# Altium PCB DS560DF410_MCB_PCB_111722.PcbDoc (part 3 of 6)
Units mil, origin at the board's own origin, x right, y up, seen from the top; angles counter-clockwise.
Board outline 5500 x 5000 mil, 6 copper layers (Top Layer, L2_GND1, L3_SIG1, L4_PWR1, L5_GND2, Bottom Layer), stack 61.748 mil thick; 297 components, 231 nets, 1236 pads, 998 vias.
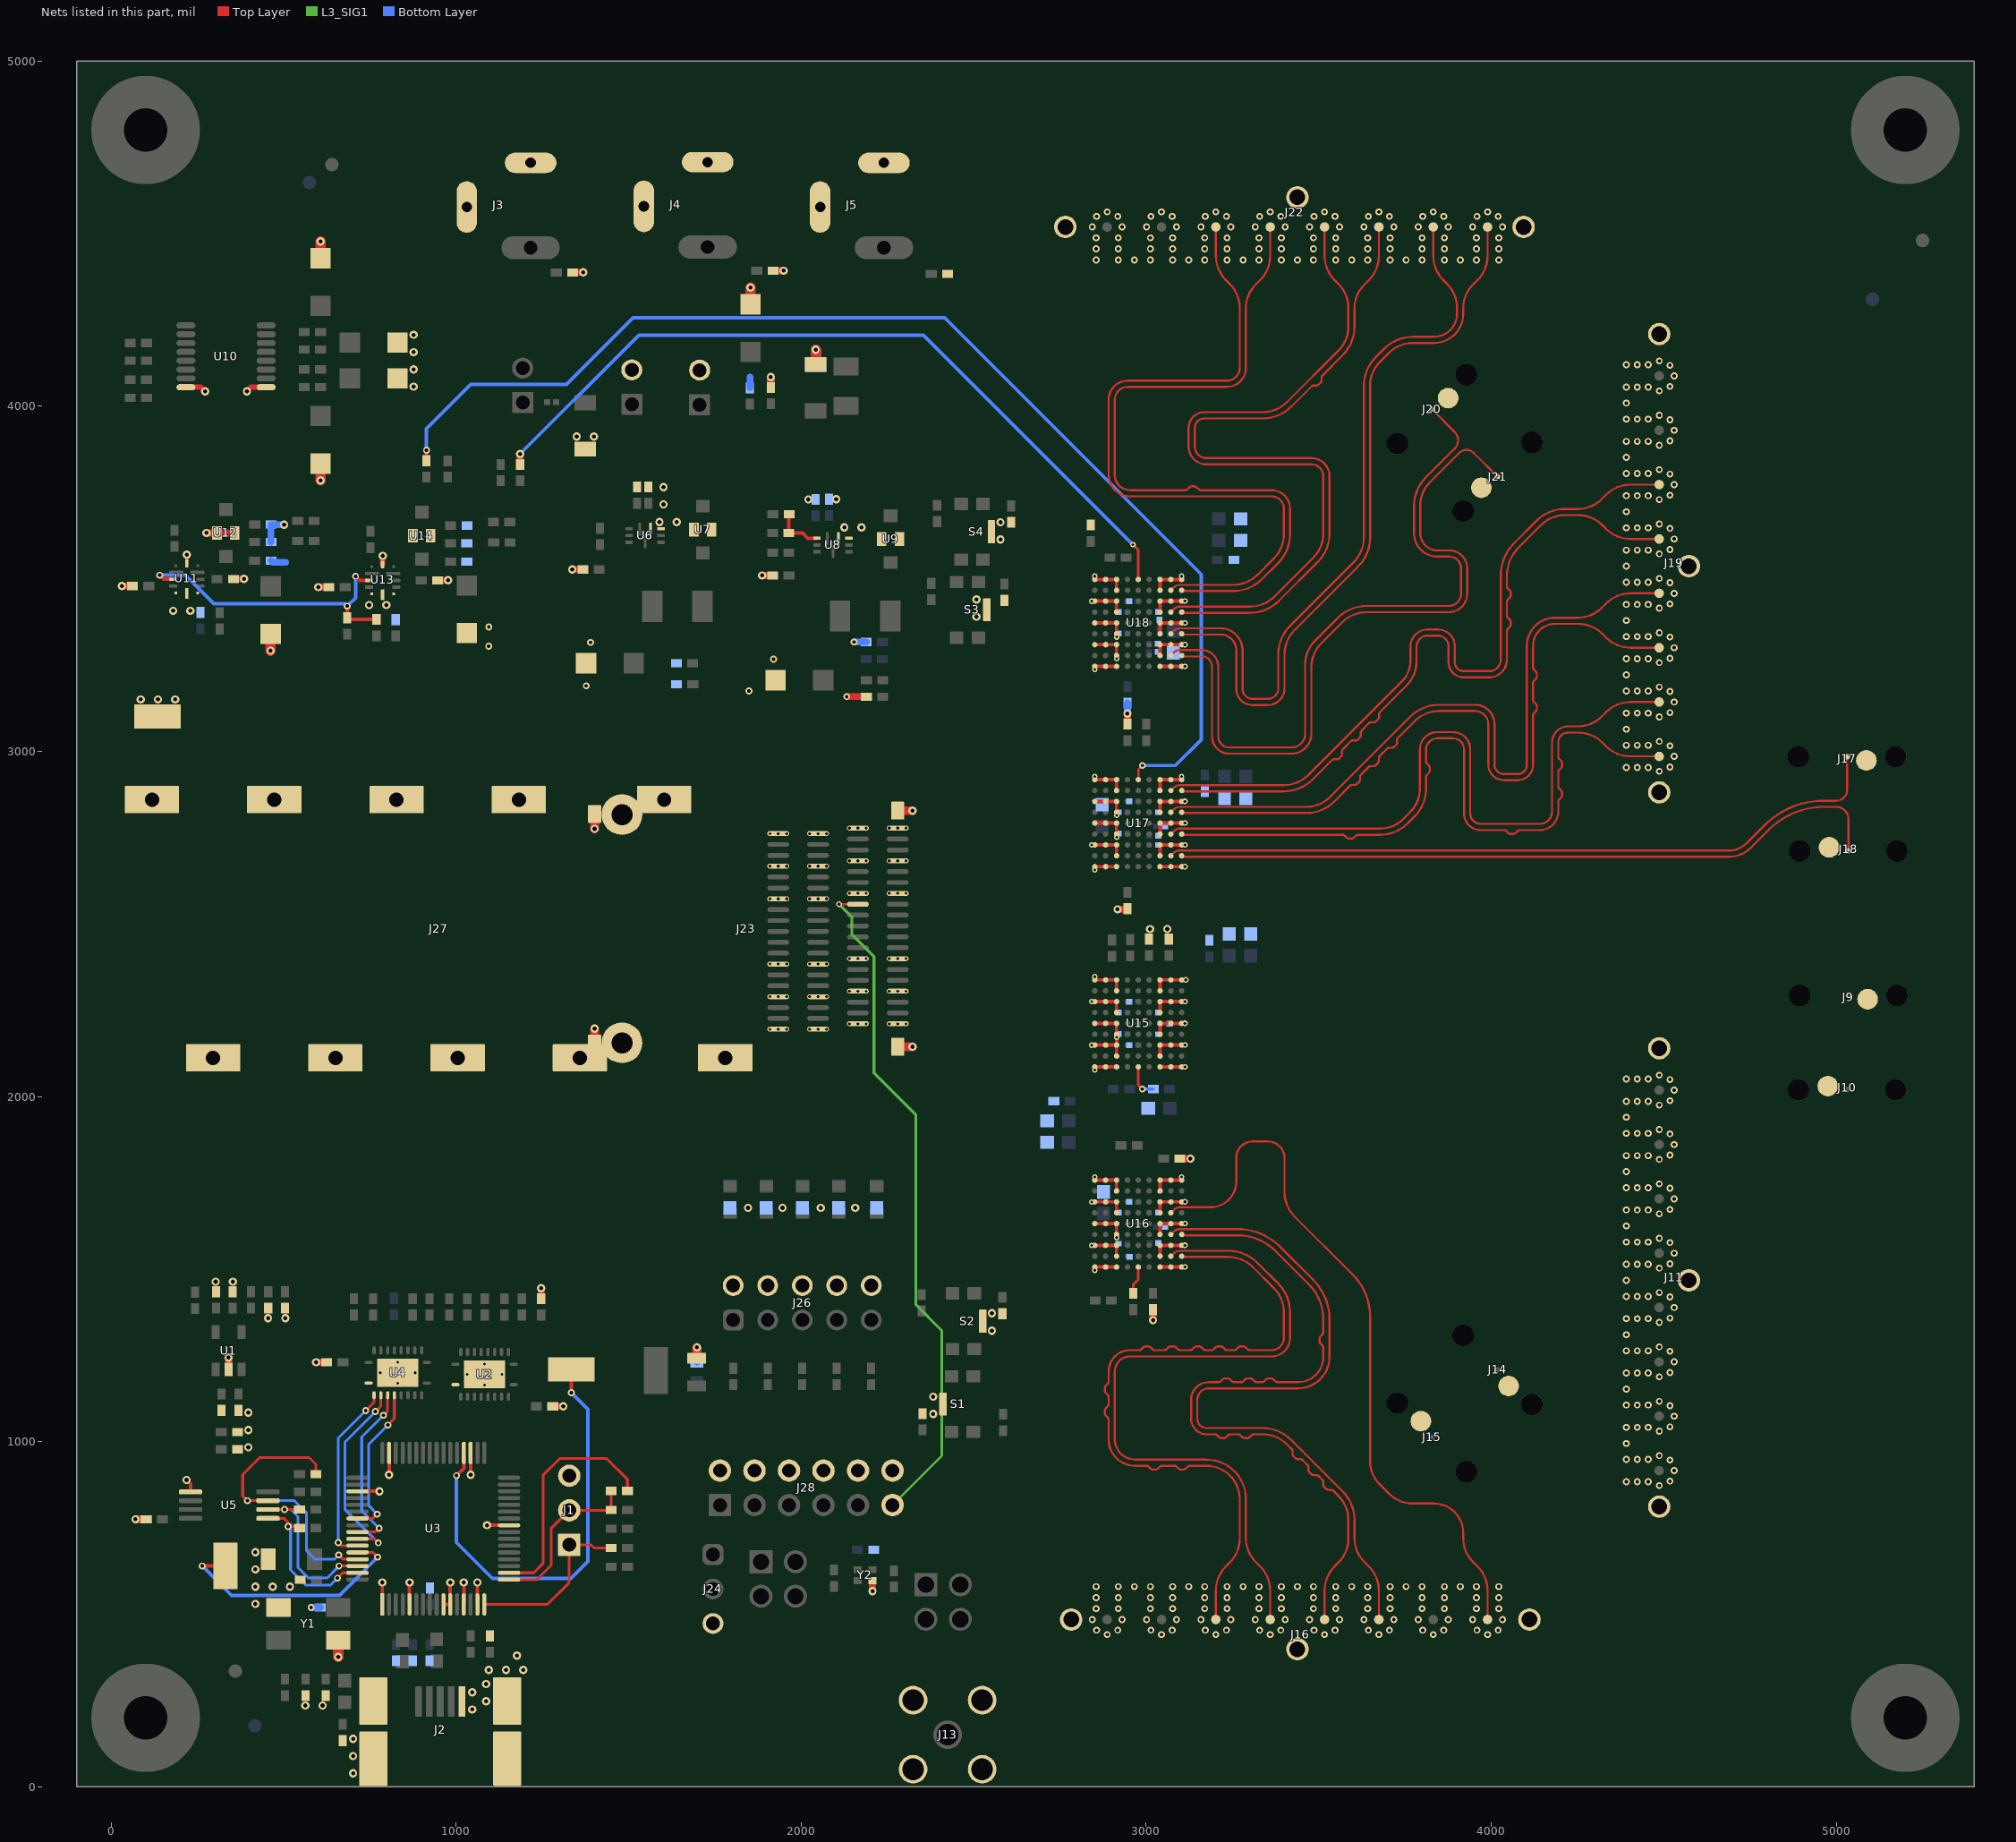
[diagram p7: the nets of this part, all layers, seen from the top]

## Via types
v1: diameter 20, hole 10, Top Layer to Bottom Layer, 380 vias
v2: diameter 24, hole 12, Top Layer to Bottom Layer, tented both sides, 226 vias
v3: diameter 20, hole 10, Top Layer to Bottom Layer, tented both sides, 162 vias
v4: diameter 14, hole 8.1, Top Layer to Bottom Layer, tented both sides, 88 vias
v5: diameter 16, hole 8.1, Top Layer to Bottom Layer, tented both sides, 84 vias
v6: diameter 16, hole 8, Top Layer to Bottom Layer, tented both sides, 34 vias
v7: diameter 15, hole 8.1, Top Layer to Bottom Layer, tented both sides, 16 vias
v8: diameter 19.68, hole 7.87, Top Layer to Bottom Layer, tented both sides, 8 vias

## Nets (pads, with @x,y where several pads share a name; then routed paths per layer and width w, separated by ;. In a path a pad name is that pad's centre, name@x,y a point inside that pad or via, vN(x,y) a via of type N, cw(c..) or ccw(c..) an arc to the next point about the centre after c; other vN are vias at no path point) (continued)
CON_RX6P: J16.1 U16.H6 | length 2123.7
  Top Layer w6: U16.H6@3071.49,1663.14 3079.81,1671.46 cw(c3097.74,1653.53) 3097.74,1678.89 3185.79,1678.89 ccw(c3185.79,1754.2) 3261.1,1754.2 3261.1,1820.78 ; 3261.1,1822.78 cw(c3308,1822.78) 3308,1869.68 3352.58,1869.68 cw(c3352.58,1821.46) 3400.8,1821.46 3400.8,1722.87 ccw(c3500.8,1722.87) 3430.09,1652.16 3598.79,1483.46 cw(c3478.3,1362.97) 3648.7,1362.97 3648.7,945.32 ccw(c3748.7,945.32) 3677.99,874.61 3702.68,849.92 ccw(c3773.39,920.63) 3773.39,820.63 3834.08,820.63 cw(c3834.08,735.95) 3918.76,735.95 3918.76,719.64 ccw(c4014.95,719.64) 3946.93,651.62 3960,638.56 cw(c3889.29,567.85) 3989.29,567.85 J16.1@3989.29,484.47
CON_RX7N: J16.4 U16.J4 | length 2125.8
  Top Layer w6: U16.J4@3102.98,1600.15 ccw(c3108.42,1605.59) 3108.42,1597.9 3265.01,1597.9 cw(c3265.01,1443.66) 3374.08,1552.72 3471.4,1455.4 cw(c3370.5,1354.49) 3513.2,1354.49 3513.2,1316.68 cw(c3504.47,1316.68) 3510.64,1310.5 3505.84,1305.7 ccw(c3514.81,1296.73) 3502.12,1296.73 3502.12,1291.46 ccw(c3514.36,1291.46) 3505.7,1282.81 3510.64,1277.88 cw(c3504.47,1271.7) 3513.2,1271.7 3513.2,1245.49 cw(c3439.97,1245.49) 3439.97,1172.26 3380.58,1172.26 cw(c3380.58,1180.99) 3374.4,1174.82 3369.6,1179.62 ccw(c3360.63,1170.65) 3360.63,1183.34 3355.36,1183.34 ccw(c3355.36,1171.1) 3346.71,1179.75 3341.78,1174.82 cw(c3335.6,1180.99) 3335.6,1172.26 3320.18,1172.26 cw(c3320.18,1180.99) 3314,1174.82 3309.2,1179.62 ccw(c3300.23,1170.65) 3300.23,1183.34 3294.96,1183.34 ccw(c3294.96,1171.1) 3286.31,1179.75 3281.38,1174.82 cw(c3275.2,1180.99) 3275.2,1172.26 3254.68,1172.26 cw(c3254.68,1180.99) 3248.5,1174.82 3243.7,1179.62 ccw(c3234.73,1170.65) 3234.73,1183.34 3229.46,1183.34 ccw(c3229.46,1171.1) 3220.81,1179.75 3215.88,1174.82 cw(c3209.7,1180.99) 3209.7,1172.26 3181.41,1172.26 ccw(c3181.41,1120.85) 3130,1120.85 3130,1066.4 ccw(c3175.2,1066.4) 3175.2,1021.2 3198.9,1021.2 cw(c3198.9,1012.47) 3205.08,1018.64 3210.01,1013.7 ccw(c3218.66,1022.36) 3218.66,1010.12 3223.93,1010.12 ccw(c3223.93,1022.81) 3232.9,1013.84 3237.7,1018.64 cw(c3243.88,1012.47) 3243.88,1021.2 3266.8,1021.2 cw(c3266.8,1012.47) 3272.98,1018.64 3277.91,1013.7 ccw(c3286.56,1022.36) 3286.56,1010.12 3291.83,1010.12 ccw(c3291.83,1022.81) 3300.8,1013.84 3305.6,1018.64 cw(c3311.78,1012.47) 3311.78,1021.2 3337.18,1021.2 cw(c3337.18,921.2) 3407.89,991.91 3421.43,978.37 cw(c3415.25,972.2) 3423.99,972.2 3423.99,965.21 ccw(c3436.22,965.21) 3427.57,956.56 3431.29,952.84 ccw(c3440.26,961.81) 3440.26,949.12 3447.06,949.12 cw(c3447.06,940.39) 3453.23,946.57 3467.74,932.06 cw(c3461.57,925.88) 3470.3,925.88 3470.3,918.9 ccw(c3482.54,918.9) 3473.89,910.25 3477.61,906.52 ccw(c3486.58,915.49) 3486.58,902.81 3493.37,902.81 cw(c3493.37,894.07) 3499.55,900.25 3510.45,889.35 cw(c3504.28,883.17) 3513.01,883.17 3513.01,876.19 ccw(c3525.25,876.19) 3516.59,867.54 3520.32,863.81 ; J16.4@3516.84,484.47 3516.84,567.85 cw(c3616.84,567.85) 3546.13,638.56 3556.51,648.93 ccw(c3485.8,719.64) 3585.8,719.64 3585.8,772.58 ccw(c3485.8,772.58) 3556.51,843.29 3542.26,857.54 ccw(c3536.08,851.37) 3536.08,860.1 3529.29,860.1 cw(c3529.29,872.78) 3520.33,863.8
CON_RX7P: J16.3 U16.H4 | length 2125.4
  Top Layer w6: U16.H4@3071.49,1600.15 3079.81,1608.47 cw(c3097.74,1590.54) 3097.74,1615.9 3265.01,1615.9 cw(c3265.01,1443.66) 3386.8,1565.46 3484.13,1468.12 cw(c3370.5,1354.49) 3531.2,1354.49 3531.2,1245.49 cw(c3439.97,1245.49) 3439.97,1154.26 3181.41,1154.26 ; J16.3@3674.33,484.47 3674.33,567.85 ccw(c3574.33,567.85) 3645.04,638.56 3631.97,651.62 cw(c3699.99,719.64) 3603.8,719.64 3603.8,772.58 ccw(c3485.8,772.58) 3569.24,856.02 3420.61,1004.64 ccw(c3337.18,921.2) 3337.18,1039.2 3175.2,1039.2 cw(c3175.2,1066.4) 3148,1066.4 3148,1120.85 cw(c3181.41,1120.85) 3181,1154.26 ; 3181,1154.26 cw(c3181.41,1120.85) 3181.41,1154.26 ; 3181,1154.26 3181.41,1154.26
CON_RX8N: J16.6 U16.J2 | length 2126.2
  Top Layer w6: U16.J2@3102.98,1537.16 ccw(c3108.42,1542.59) 3108.42,1534.91 3238.37,1534.91 cw(c3238.37,1434.91) 3309.08,1505.62 3369.61,1445.09 cw(c3298.9,1374.38) 3398.9,1374.38 3398.9,1300.5 cw(c3363.4,1300.5) 3363.4,1265 3300.18,1265 cw(c3300.18,1273.73) 3294,1267.56 3289.07,1272.5 ccw(c3280.42,1263.84) 3280.42,1276.08 3275.15,1276.08 ccw(c3275.15,1263.39) 3266.18,1272.36 3261.38,1267.56 cw(c3255.2,1273.73) 3255.2,1265 3234.18,1265 cw(c3234.18,1273.73) 3228,1267.56 3223.07,1272.5 ccw(c3214.42,1263.84) 3214.42,1276.08 3209.15,1276.08 ccw(c3209.15,1263.39) 3200.18,1272.36 3195.38,1267.56 cw(c3189.2,1273.73) 3189.2,1265 3172.18,1265 cw(c3172.18,1273.73) 3166,1267.56 3161.07,1272.5 ccw(c3152.42,1263.84) 3152.42,1276.08 3147.15,1276.08 ccw(c3147.15,1263.39) 3138.18,1272.36 3133.38,1267.56 cw(c3127.2,1273.73) 3127.2,1265 3097.8,1265 cw(c3097.8,1273.73) 3091.62,1267.56 3086.82,1272.36 ccw(c3077.85,1263.39) 3077.85,1276.08 3072.58,1276.08 ccw(c3072.58,1263.84) 3063.93,1272.5 3059,1267.56 cw(c3052.82,1273.73) 3052.82,1265 3024.68,1265 cw(c3024.68,1273.73) 3018.5,1267.56 3013.57,1272.5 ccw(c3004.92,1263.84) 3004.92,1276.08 2999.65,1276.08 ccw(c2999.65,1263.39) 2990.68,1272.36 2985.88,1267.56 cw(c2979.7,1273.73) 2979.7,1265 2953.47,1265 ccw(c2953.47,1202.5) 2890.97,1202.5 2890.97,1173.9 cw(c2882.24,1173.9) 2888.41,1167.72 2883.6,1162.92 ccw(c2892.57,1153.95) 2879.89,1153.95 2879.89,1148.68 ccw(c2892.12,1148.68) 2883.47,1140.03 2888.41,1135.1 cw(c2882.24,1128.92) 2890.97,1128.92 2890.97,1108.4 cw(c2882.24,1108.4) 2888.41,1102.22 2883.6,1097.42 ccw(c2892.57,1088.45) 2879.89,1088.45 2879.89,1083.18 ccw(c2892.12,1083.18) 2883.47,1074.53 2888.41,1069.6 cw(c2882.24,1063.42) 2890.97,1063.42 2890.97,1006.51 ccw(c2967.58,1006.51) 2967.58,929.9 3000.7,929.9 cw(c3000.7,921.17) 3006.88,927.34 3011.68,922.54 ccw(c3020.65,931.51) 3020.65,918.82 3025.92,918.82 ccw(c3025.92,931.06) 3034.57,922.4 3039.5,927.34 cw(c3045.68,921.17) 3045.68,929.9 3081.9,929.9 cw(c3081.9,921.17) 3088.08,927.34 3092.88,922.54 ccw(c3101.85,931.51) 3101.85,918.82 3107.12,918.82 ccw(c3107.12,931.06) 3115.77,922.4 3120.7,927.34 cw(c3126.88,921.17) 3126.88,929.9 3174.38,929.9 cw(c3174.38,833.45) 3270.84,833.45 3270.84,719.64 cw(c3170.84,719.64) 3241.55,648.93 3231.17,638.56 ccw(c3301.88,567.85) 3201.88,567.85 J16.6@3201.88,484.47
CON_RX8P: J16.5 U16.H2 | length 2125.4
  Top Layer w6: U16.H2@3071.49,1537.16 3079.81,1545.48 cw(c3097.74,1527.55) 3097.74,1552.9 3238.37,1552.9 cw(c3238.37,1434.9) 3321.81,1518.35 3382.34,1457.81 cw(c3298.9,1374.38) 3416.9,1374.38 3416.9,1300.5 cw(c3363.4,1300.5) 3363.4,1247 2953.47,1247 ccw(c2953.47,1202.5) 2908.97,1202.5 2908.97,1006.51 ccw(c2967.58,1006.51) 2967.58,947.9 3174.38,947.9 cw(c3174.38,833.45) 3288.84,833.45 3288.84,719.64 ccw(c3385.03,719.64) 3317.01,651.62 3330.08,638.56 cw(c3259.36,567.85) 3359.36,567.85 J16.5@3359.36,484.47
CON_TX1N: J18.1 U17.A8 | length 2089.6
  Top Layer w6: U17.A8@3102.98,2697.39 ccw(c3110.46,2704.87) 3110.46,2694.3 4688.28,2694.3 ccw(c4688.28,2785.13) 4752.5,2720.9 4786.71,2755.11 ; 4788.19,2756.59 4804.42,2772.82 cw(c4963.58,2613.66) 4963.58,2838.75 5000.56,2838.75 cw(c5000.56,2804.43) 5034.89,2804.43 J18.1@5034.89,2711.31
CON_TX1P: J17.1 U17.B8 | length 2125.2
  Top Layer w6: U17.B8@3071.49,2697.39 3081.33,2707.23 cw(c3093.68,2694.88) 3093.68,2712.35 3114.94,2712.35 ; 3115.38,2712.3 4688.27,2712.3 ccw(c4688.27,2785.13) 4739.78,2733.63 4791.72,2785.57 cw(c4963.55,2613.74) 4963.55,2856.75 5000.56,2856.75 ccw(c5000.56,2887.34) 5031.15,2887.34 J17.1@5031.15,2984.18
CON_TX2N: J19.8 U17.A6 | length 2131.3
  Top Layer w6: 4082.7,2771.78 4083.34,2771.78 ; J19.8@4486.77,2985.27 4403.39,2985.27 cw(c4403.39,3085.27) 4332.68,3014.56 4322.31,3024.94 ccw(c4251.6,2954.23) 4251.6,3054.23 4222.65,3054.23 ccw(c4222.65,3025.58) 4194,3025.58 4194,2984.62 ccw(c4202.73,2984.62) 4196.56,2978.45 4201.42,2973.59 cw(c4192.58,2964.75) 4205.08,2964.75 4205.08,2959.52 cw(c4192.58,2959.52) 4201.42,2950.68 4196.56,2945.82 ccw(c4202.73,2939.65) 4194,2939.65 4194,2898.99 ccw(c4202.73,2898.99) 4196.56,2892.82 4201.42,2887.96 cw(c4192.58,2879.12) 4205.08,2879.12 4205.08,2873.88 cw(c4192.58,2873.88) 4201.42,2865.05 4196.56,2860.19 ccw(c4202.73,2854.01) 4194,2854.01 4194,2824.81 cw(c4140.98,2824.81) 4140.98,2771.78 4083.34,2771.78 ; U17.A6@3108.42,2758.13 cw(c3108.42,2765.82) U17.A6@3102.98,2760.39 ccw(c3108.42,2765.82) U17.A6@3108.42,2758.13 ; U17.A6@3108.42,2758.13 3567.64,2758.13 cw(c3567.64,2746.86) 3575.61,2754.83 3579.73,2750.71 ccw(c3588.57,2759.55) 3588.57,2747.06 3593.8,2747.06 ccw(c3593.8,2759.55) 3602.64,2750.71 3606.04,2754.11 cw(c3615.74,2744.41) 3615.74,2758.13 3678.37,2758.13 ccw(c3678.37,2869.23) 3756.93,2790.67 3778.24,2811.99 ccw(c3699.17,2891.07) 3811,2891.07 3811,2925.67 cw(c3819.73,2925.67) 3813.56,2931.84 3818.42,2936.7 ccw(c3809.58,2945.54) 3822.08,2945.54 3822.08,2950.77 ccw(c3809.58,2950.77) 3818.42,2959.61 3813.56,2964.47 cw(c3819.73,2970.65) 3811,2970.65 3811,3004.85 cw(c3843.79,3004.85) 3843.79,3037.65 3889.15,3037.65 cw(c3889.15,3005.8) 3921,3005.8 3921,2819.95 ccw(c3969.17,2819.95) 3969.17,2771.78 4037.16,2771.78 cw(c4037.16,2762.78) 4043.52,2769.15 4048.31,2764.36 ccw(c4057.14,2773.2) 4057.14,2760.7 4062.38,2760.7 ccw(c4062.38,2773.2) 4071.21,2764.36 4075.3,2768.45 cw(c4083.34,2760.41) 4083.34,2771.78
CON_TX2P: J19.7 U17.B6 | length 2125.5
  Top Layer w6: U17.B6@3071.49,2760.39 3079.81,2768.71 cw(c3097.74,2750.78) 3097.74,2776.13 3678.37,2776.13 ccw(c3678.37,2869.23) 3744.2,2803.4 3765.52,2824.72 ccw(c3699.17,2891.07) 3793,2891.07 3793,3004.85 cw(c3843.79,3004.85) 3843.79,3055.65 3889.15,3055.65 cw(c3889.15,3005.8) 3939,3005.8 3939,2819.95 ccw(c3969.17,2819.95) 3969.17,2789.78 4140.98,2789.78 ccw(c4140.98,2824.81) 4176,2824.81 4176,3025.58 cw(c4222.65,3025.58) 4222.65,3072.23 4251.6,3072.23 ccw(c4251.6,3168.42) 4319.62,3100.4 4332.68,3113.46 cw(c4403.39,3042.75) 4403.39,3142.75 J19.7@4486.77,3142.75
CON_TX3N: J19.6 U17.A4 | length 2130.8
  Top Layer w6: J19.6@4486.77,3300.23 4403.39,3300.23 cw(c4403.39,3400.23) 4332.68,3329.52 4322.31,3339.9 ccw(c4251.6,3269.19) 4251.6,3369.19 4184.72,3369.19 ccw(c4184.72,3305.56) 4121.1,3305.56 4121.1,3242.9 ccw(c4129.83,3242.9) 4123.66,3236.72 4128.52,3231.86 cw(c4119.68,3223.03) 4132.18,3223.03 4132.18,3217.79 cw(c4119.68,3217.79) 4128.52,3208.96 4124.02,3204.46 ccw(c4131.07,3197.41) 4121.1,3197.41 4121.1,3149.65 ccw(c4131.64,3149.65) 4124.19,3142.2 4128.52,3137.86 cw(c4119.68,3129.03) 4132.18,3129.03 4132.18,3123.79 cw(c4119.68,3123.79) 4128.52,3114.96 4124.47,3110.9 ccw(c4132.6,3102.78) 4121.1,3102.78 4121.1,2960.95 cw(c4076.5,2960.95) 4076.5,2916.35 4036.6,2916.35 cw(c4036.6,2961.65) 3991.3,2961.65 3991.3,3078.65 ccw(c3953.2,3078.65) 3953.2,3116.75 3848.55,3116.75 ccw(c3848.55,3016.75) 3777.84,3087.46 3729.88,3039.5 ccw(c3736.61,3032.77) 3727.1,3032.77 3727.1,3026.22 cw(c3714.6,3026.22) 3723.44,3017.38 3719.73,3013.68 cw(c3710.9,3022.52) 3710.9,3010.02 3704.66,3010.02 ccw(c3704.66,2999.76) 3697.4,3007.02 3677.21,2986.82 ccw(c3684.6,2979.43) 3674.15,2979.43 3674.15,2973.27 cw(c3661.65,2973.27) 3670.49,2964.43 3666.78,2960.73 cw(c3657.95,2969.57) 3657.95,2957.07 3651.63,2957.07 ccw(c3651.63,2947) 3644.51,2954.12 3622.67,2932.28 ccw(c3629.84,2925.11) 3619.7,2925.11 3619.7,2918.82 cw(c3607.2,2918.82) 3616.04,2909.98 3612.33,2906.28 cw(c3603.5,2915.12) 3603.5,2902.62 3597.23,2902.62 ccw(c3597.23,2892.43) 3590.02,2899.64 3544.38,2853.99 cw(c3465.03,2933.34) 3465.03,2821.13 U17.A4@3108.42,2821.13 ; U17.A4@3108.42,2821.13 cw(c3108.42,2828.81) U17.A4@3102.98,2823.38 ccw(c3108.42,2828.81) U17.A4@3108.42,2821.13
CON_TX3P: J19.5 U17.B4 | length 2125.8
  Top Layer w6: U17.B4@3071.49,2823.38 3079.81,2831.7 cw(c3097.74,2813.77) 3097.74,2839.13 3465.03,2839.13 ccw(c3465.03,2933.34) 3531.65,2866.72 3765.12,3100.19 cw(c3848.55,3016.75) 3848.55,3134.75 3953.2,3134.75 cw(c3953.2,3078.65) 4009.3,3078.65 4009.3,2961.65 ccw(c4036.6,2961.65) 4036.6,2934.35 4076.5,2934.35 ccw(c4076.5,2960.95) 4103.1,2960.95 4103.1,3305.56 cw(c4184.72,3305.56) 4184.72,3387.19 4251.6,3387.19 ccw(c4251.6,3483.38) 4319.62,3415.36 4332.68,3428.43 cw(c4403.39,3357.71) 4403.39,3457.71 J19.5@4486.77,3457.71
CON_TX4N: J19.4 U17.A2 | length 2131.3
  Top Layer w6: J19.4@4486.77,3615.19 4403.39,3615.2 cw(c4403.39,3715.2) 4332.68,3644.48 4322.31,3654.86 ccw(c4251.6,3584.15) 4251.6,3684.15 4213.92,3684.15 ccw(c4213.92,3584.15) 4143.21,3654.86 4080.27,3591.92 ccw(c4164.7,3507.49) 4045.3,3507.49 4045.3,3478.5 ccw(c4054.81,3478.5) 4048.09,3471.78 4053.17,3466.69 cw(c4045.42,3458.94) 4056.38,3458.94 4056.38,3452.75 cw(c4044.65,3452.75) 4052.94,3444.46 4048.31,3439.82 ccw(c4055.56,3432.56) 4045.3,3432.56 4045.3,3393.9 ccw(c4054.81,3393.9) 4048.09,3387.18 4052.97,3382.29 cw(c4044.75,3374.07) 4056.38,3374.07 4056.38,3367.96 cw(c4045.11,3367.96) 4053.08,3359.99 4048.31,3355.22 ccw(c4055.56,3347.96) 4045.3,3347.96 4045.3,3265.67 cw(c3993.77,3265.67) 3993.77,3214.15 3920.5,3214.15 cw(c3920.5,3258.45) 3876.2,3258.45 3876.2,3304.42 ccw(c3845.48,3304.42) 3845.48,3335.15 3815.92,3335.15 ccw(c3815.92,3302.62) 3783.4,3302.62 3783.4,3260.28 cw(c3685.07,3260.28) 3754.6,3190.74 3677.57,3113.71 ccw(c3684.29,3106.99) 3674.78,3106.99 3674.78,3099.35 cw(c3664.91,3099.35) 3671.89,3092.37 3667.27,3087.75 cw(c3658.79,3096.23) 3658.79,3084.24 3652.34,3084.24 ccw(c3652.34,3073.97) 3645.09,3081.23 3624.89,3061.04 ccw(c3632.28,3053.65) 3621.83,3053.65 3621.83,3046.95 cw(c3610.64,3046.95) 3618.55,3039.03 3613.71,3034.18 cw(c3606.71,3041.18) 3606.71,3031.29 3599.31,3031.29 ccw(c3599.31,3021.22) 3592.19,3028.34 3570.35,3006.5 ccw(c3577.52,2999.33) 3567.38,2999.33 3567.38,2992.14 cw(c3557.04,2992.14) 3564.36,2984.84 3559.22,2979.7 cw(c3552.32,2986.6) 3552.32,2976.84 3544.91,2976.84 ccw(c3544.91,2966.65) 3537.71,2973.85 3482.53,2918.67 cw(c3399.1,3002.12) 3399.1,2884.12 U17.A2@3108.42,2884.12 ; U17.A2@3108.42,2884.12 cw(c3108.42,2891.81) U17.A2@3102.98,2886.37 ccw(c3108.42,2891.81) U17.A2@3108.42,2884.12
CON_TX4P: J19.3 U17.B2 | length 2125.5
  Top Layer w6: U17.B2@3071.49,2886.37 3079.81,2894.69 cw(c3097.74,2876.76) 3097.74,2902.12 3399.1,2902.12 ccw(c3399.1,3002.12) 3469.81,2931.41 3741.87,3203.47 ccw(c3685.07,3260.28) 3765.4,3260.28 3765.4,3302.62 cw(c3815.92,3302.62) 3815.92,3353.15 3845.47,3353.15 cw(c3845.47,3304.42) 3894.2,3304.42 3894.2,3258.45 ccw(c3920.5,3258.45) 3920.5,3232.15 3993.77,3232.15 ccw(c3993.77,3265.67) 4027.3,3265.67 4027.3,3507.49 cw(c4164.7,3507.49) 4067.54,3604.64 4130.49,3667.59 cw(c4213.92,3584.15) 4213.92,3702.15 4251.6,3702.15 ccw(c4251.6,3798.34) 4319.62,3730.32 4332.68,3743.39 cw(c4403.39,3672.68) 4403.39,3772.68 J19.3@4486.77,3772.68
CON_TX5N: J21.1 U18.A8 | length 2100.4
  Top Layer w6: U18.A8@3102.98,3277.51 ccw(c3109.86,3284.39) 3109.86,3274.66 3167.37,3274.66 cw(c3161.99,3247.89) 3181.3,3267.2 cw(c3158.36,3244.27) 3190.8,3244.27 3190.8,3223.44 3190.8,3043.04 ccw(c3240.6,3043.04) 3240.6,2993.24 3421.3,2993.24 ccw(c3421.3,3050.54) 3478.6,3050.54 3478.6,3243.02 cw(c3578.6,3243.02) 3507.89,3313.73 3567.91,3373.76 cw(c3638.62,3303.04) 3638.62,3403.04 3876.1,3403.04 ccw(c3876.1,3457.35) 3930.4,3457.35 3930.4,3529.72 ccw(c3877.98,3529.72) 3877.98,3582.14 3844.15,3582.14 cw(c3844.15,3632.3) 3794,3632.3 3794,3710.28 cw(c3894,3710.28) 3823.29,3780.99 3906.48,3864.18 cw(c3928.11,3842.55) 3949.74,3864.18 J21.1@4018.22,3795.71
CON_TX5P: J20.1 U18.B8 | length 2125.4
  Top Layer w6: U18.B8@3071.49,3277.51 3079.81,3285.83 cw(c3097.74,3267.9) 3097.74,3293.26 3161.91,3293.26 cw(c3161.91,3247.91) 3193.98,3279.98 cw(c3158.36,3244.27) 3208.8,3244.27 3208.8,3043.04 ccw(c3240.6,3043.04) 3240.6,3011.24 3421.3,3011.24 ccw(c3421.3,3050.54) 3460.59,3049.81 3460.59,3250.47 cw(c3560.59,3250.47) 3489.88,3321.18 3555.19,3386.49 cw(c3638.62,3303.04) 3638.62,3421.04 3876.1,3421.04 ccw(c3876.1,3457.35) 3912.4,3457.35 3912.4,3529.72 ccw(c3877.98,3529.72) 3877.98,3564.14 3844.15,3564.14 cw(c3844.15,3632.3) 3776,3632.3 3776,3710.28 cw(c3894,3710.28) 3810.56,3793.72 3893.75,3876.91 ccw(c3869.48,3901.18) 3893.75,3925.45 J20.1@3827.91,3991.29
CON_TX6N: J22.8 U18.A6 | length 2115.9
  Top Layer w6: U18.A6@3102.98,3340.5 ccw(c3108.42,3345.94) 3108.42,3338.25 3215.51,3338.25 cw(c3215.51,3292.66) 3261.1,3292.66 3261.1,3182.87 ; 3261.1,3180.87 ccw(c3308,3180.87) 3308,3133.97 3352.58,3133.97 ccw(c3352.58,3182.18) 3400.8,3182.18 3400.8,3280.77 cw(c3500.8,3280.77) 3430.09,3351.49 3614.14,3535.54 ccw(c3530.7,3618.97) 3648.7,3618.97 3648.7,4058.32 cw(c3748.7,4058.32) 3677.99,4129.03 3702.68,4153.72 cw(c3773.39,4083.01) 3773.39,4183.01 3834.08,4183.01 ccw(c3834.08,4267.69) 3918.76,4267.69 3918.76,4284 cw(c4014.95,4284) 3946.93,4352.02 3960,4365.09 ccw(c3889.29,4435.8) 3989.29,4435.8 J22.8@3989.29,4519.18
CON_TX6P: J22.7 U18.B6 | length 2125.2
  Top Layer w6: U18.B6@3071.49,3340.5 3079.81,3348.83 cw(c3097.74,3330.9) 3097.74,3356.25 3215.51,3356.25 cw(c3215.51,3292.66) 3279.1,3292.66 3279.1,3180.87 ccw(c3308,3180.87) 3308,3151.97 3352.58,3151.97 ccw(c3352.58,3182.18) 3382.8,3182.18 3382.8,3280.77 cw(c3500.8,3280.77) 3417.36,3364.21 3601.41,3548.26 ccw(c3530.7,3618.97) 3630.7,3618.97 3630.7,4058.32 cw(c3748.7,4058.32) 3665.26,4141.76 3689.96,4166.46 cw(c3773.39,4083.01) 3773.39,4201.01 3834.08,4201.01 ccw(c3834.08,4267.69) 3900.76,4267.69 3900.76,4284 ccw(c3800.76,4284) 3871.47,4354.71 3861.09,4365.09 cw(c3931.81,4435.8) 3831.81,4435.8 J22.7@3831.81,4519.18
CON_TX7N: J22.6 U18.A4 | length 2125.4
  Top Layer w6: U18.A4@3102.98,3403.5 ccw(c3108.42,3408.93) 3108.42,3401.24 3300.98,3401.24 ccw(c3300.98,3519.24) 3384.41,3435.8 3496.64,3548.03 ccw(c3413.2,3631.47) 3531.2,3631.47 3531.2,3797.19 ccw(c3479,3797.19) 3479,3849.39 3174.41,3849.39 cw(c3174.41,3882.8) 3141,3882.8 3141,3937.24 cw(c3168.2,3937.24) 3168.2,3964.44 3337.18,3964.44 ccw(c3337.18,4082.44) 3420.61,3999 3478.93,4057.32 cw(c3485.1,4051.14) 3485.1,4059.87 3492.09,4059.87 ccw(c3492.09,4072.11) 3500.74,4063.46 3504.46,4067.18 ccw(c3495.49,4076.15) 3508.18,4076.15 3508.18,4082.95 cw(c3516.91,4082.95) 3510.73,4089.12 3569.24,4147.63 ccw(c3485.8,4231.06) 3603.8,4231.06 3603.8,4284 cw(c3699.99,4284) 3631.97,4352.02 3645.04,4365.09 ccw(c3574.33,4435.8) 3674.33,4435.8 J22.6@3674.32,4519.18
CON_TX7P: J22.5 U18.B4 | length 2125.2
  Top Layer w6: U18.B4@3071.49,3403.5 3079.81,3411.82 cw(c3097.74,3393.89) 3097.74,3419.24 3300.98,3419.24 ccw(c3300.98,3519.24) 3371.69,3448.53 3483.91,3560.76 ccw(c3413.2,3631.47) 3513.2,3631.47 3513.2,3797.19 ccw(c3479,3797.19) 3479,3831.39 3174.41,3831.39 cw(c3174.41,3882.8) 3123,3882.8 3123,3937.24 cw(c3168.2,3937.24) 3168.2,3982.44 3337.18,3982.44 ccw(c3337.18,4082.44) 3407.89,4011.73 3556.51,4160.35 ccw(c3485.8,4231.06) 3585.8,4231.06 3585.8,4284 ccw(c3485.8,4284) 3556.51,4354.71 3546.13,4365.09 cw(c3616.84,4435.8) 3516.84,4435.8 J22.5@3516.84,4519.18
CON_TX8N: J22.4 U18.A2 | length 2125.4
  Top Layer w6: U18.A2@3102.98,3466.49 ccw(c3108.42,3471.92) 3108.42,3464.24 3251.87,3464.24 ccw(c3251.87,3582.24) 3335.3,3498.79 3382.34,3545.83 ccw(c3298.9,3629.27) 3416.9,3629.27 3416.9,3703.14 ccw(c3363.4,3703.14) 3363.4,3756.64 3157.87,3756.64 cw(c3157.87,3765.38) 3151.69,3759.2 3146.76,3764.14 ccw(c3138.11,3755.49) 3138.11,3767.72 3132.84,3767.72 ccw(c3132.84,3755.04) 3123.87,3764.01 3119.06,3759.2 cw(c3112.89,3765.38) 3112.89,3756.64 2953.47,3756.64 cw(c2953.47,3801.14) 2908.97,3801.14 2908.97,4018.44 cw(c2946.27,4018.44) 2946.27,4055.74 3233.5,4055.74 ccw(c3233.5,4111.08) 3288.84,4111.08 3288.84,4284 cw(c3385.03,4284) 3317.01,4352.02 3330.08,4365.09 ccw(c3259.36,4435.8) 3359.36,4435.8 J22.4@3359.36,4519.18
CON_TX8P: J22.3 U18.B2 | length 2125.2
  Top Layer w6: U18.B2@3071.49,3466.49 3079.81,3474.81 cw(c3097.74,3456.88) 3097.74,3482.24 3251.87,3482.24 ccw(c3251.87,3582.24) 3322.58,3511.53 3369.61,3558.56 ccw(c3298.9,3629.27) 3398.9,3629.27 3398.9,3703.14 ccw(c3363.4,3703.14) 3363.4,3738.64 2953.47,3738.64 cw(c2953.47,3801.14) 2890.97,3801.14 2890.97,4018.44 cw(c2946.27,4018.44) 2946.27,4073.74 3233.5,4073.74 ccw(c3233.5,4111.08) 3270.84,4111.08 3270.84,4284 ccw(c3170.84,4284) 3241.55,4354.71 3231.17,4365.09 cw(c3301.88,4435.8) 3201.88,4435.8 J22.3@3201.88,4519.17
D4: U3.55 U4.15 | length 447.6
  Top Layer w8: U3.55@714.33,777.34 758.82,777.34 v3(771.35,789.88) ; v3(802.2,1048) 821.17,1066.97 U4.15@821.17,1134.47
  Bottom Layer w8: v3(771.35,789.88) 747,814.22 747,992.8 v3(802.2,1048)
D5: U3.57 U4.14 | length 505
  Top Layer w8: U3.57@714.33,737.97 765.97,737.97 v3(777,749) ; v3(789.51,1076.36) 801.49,1088.34 801.49,1097.78 801.17,1098.09 801.17,1134.15 U4.14@801.49,1134.47
  Bottom Layer w8: v3(777,749) 726.4,799.6 726.4,1013.25 v3(789.51,1076.36)
D6: U3.58 U4.13 | length 575.6
  Top Layer w8: U3.58@714.33,718.29 762.71,718.29 v3(774.45,706.55) ; v3(766.32,1087.05) 781.8,1102.53 U4.13@781.8,1134.47
  Bottom Layer w8: v3(766.32,1087.05) 760.09,1080.81 760.09,1080.65 747.2,1067.76 747.04,1067.76 678.4,999.12 678.4,802.6 v3(774.45,706.55)
D7: U3.59 U4.12 | length 529.6
  Top Layer w8: v3(658.43,707.4) 667.22,698.6 U3.59@714.33,698.6 ; v3(738.09,1089.76) 762.12,1113.79 U4.12@762.12,1134.47
  Bottom Layer w8: v3(658.43,707.4) 658.43,1010.1 v3(738.09,1089.76)
EN_1P2V_2: R20.2 R21.2 U8.4 | length 142.4
  Top Layer w10: R20.2@1965.38,3687.1 1964.51,3686.23 R21.2@1964.51,3632.35 2004.34,3632.35 2019.36,3617.33 U8.4@2045.62,3617.33
EN_1P8V: R26.2 R31.2 U11.3 U13.3 | length 885.8
  Top Layer w10: v3(140.95,3510.27) 152.68,3498.54 U11.3@180.17,3498.54 ; v3(684.55,3420.8) R26.2@684.55,3386.88 689.49,3381.95 R31.2@769.4,3381.95 ; v3(708.57,3507.04) 720.3,3495.3 U13.3@747.79,3495.3
  Bottom Layer w10: v3(140.95,3510.27) 214.62,3510.27 297.59,3427.3 678.06,3427.3 v3(684.55,3420.8) 708.57,3444.82 v3(708.57,3507.04)
EN_SMB_1: R54.1 U15.E1 | length 100.9
  Top Layer w8: U15.E1@2977,2085.78 2977,2033.42 v3(2988.84,2021.58)
  Bottom Layer w8: v3(2988.84,2021.58) R54.1@3020.62,2021.58
EN_SMB_2: R66.1 U16.E1 | length 82
  Top Layer w8: R66.1@2962.95,1429.45 2962.95,1455.73 2977,1469.78 U16.E1@2977,1505.66
EN_SMB_3: R76.1 U17.E1 | length 3505.3
  Top Layer w6: U17.E1@2977,2917.87 2977,2946.73 v3(2989.1,2958.82)
  Top Layer w10: R76.1@914.21,3841.95 v3(914.21,3872.52)
  Bottom Layer w10: v3(914.21,3872.52) 914.21,3935.08 1042.47,4063.35 1320.12,4063.35 1512.7,4255.93 2415.95,4255.93 3159.3,3512.58 3159.3,3033.3 3084.82,2958.82 v3(2989.1,2958.82)
EN_SMB_4: R86.1 U18.E1 | length 2307.8
  Top Layer w8: v6(2961.62,3598.8) 2977,3583.42 U18.E1@2977,3497.98
  Top Layer w20: R86.1@1185.47,3831.01 v2(1185.47,3861.57)
  Bottom Layer w10: v2(1185.47,3861.57) 1529.63,4205.73 2354.7,4205.73 v6(2961.62,3598.8)
ePPS/CLOCK: J23.69 J28.11 | length 1977.6
  Top Layer w7.3: v6(2109.87,2556.87) J23.69@2164.37,2556.87
  L3_SIG1 w8: v6(2109.87,2556.87) 2146.43,2520.31 2146.43,2469.75 2211.07,2405.1 2211.07,2068.15 2332.68,1946.55 2332.68,1396.47 2407.43,1321.72 2407.43,958.82 J28.11@2264.72,816.12
FTDI_EECLK: R10.1 U3.62 U5.2 | length 485.3
  Top Layer w8: U5.2@454.84,803.24 v3(502.96,803.24) R10.1@546.28,803.24 ; v3(660.75,639.55) U3.62@714.33,639.55
  Bottom Layer w8: v3(502.96,803.24) 520.88,803.24 541.54,782.59 541.54,635.54 571.95,605.12 626.36,605.12 v3(660.75,639.55)
FTDI_EECS: R12.1 U3.63 U5.1 | length 478.4
  Top Layer w8: U5.1@454.84,777.65 500.6,777.65 513.25,765 v3(513.25,753.85) 541.82,753.85 R12.1@546.28,749.39 ; v3(656.15,604.6) 671.41,619.86 U3.63@714.33,619.86
  Bottom Layer w8: v3(513.25,753.85) 513.25,754.04 519.91,760.7 520.3,760.31 520.3,628.5 564.1,584.7 636.25,584.7 v3(656.15,604.6)
FTDI_EEDATA: R13.1 U3.61 U5.3 | length 873.6
  Top Layer w8: U5.3@454.84,828.83 v3(395.24,828.83) 381.57,842.5 381.57,904.68 430.85,953.95 574.07,953.95 593.52,934.51 R13.1@593.52,906 ; v3(659.65,671.68) 672.09,659.23 U3.61@714.33,659.23
  Bottom Layer w8: v3(395.24,828.83) 531.42,828.83 566.75,793.5 566.75,683.8 590.97,659.57 647.55,659.57 v3(659.65,671.68)
FTDI_PWREN: TP1.1 U3.60 | length 721
  Top Layer w8: U3.60@714.33,678.92 759.11,678.92 v3(772.75,665.28)
  Top Layer w10: v3(264.42,639.55) TP1.1@332.14,639.55
  Bottom Layer w10: v3(264.42,639.55) 349.24,554.72 662.2,554.72 v3(772.75,665.28)
FTDI_SCLK: J1.1 R2.2 U3.16 | length 507.5
  Top Layer w8: U3.16@1081.45,528.33 1264.58,528.33 1328,591.75 J1.1@1328,701.13 1390.77,701.13 1399.97,691.93 1449.18,691.93 R2.2@1449.38,692.13
FTDI_SDIN: R4.2 U3.18 | length 688.8
  Top Layer w8: U3.18@1153.3,619.86 1224.94,619.86 1251.75,646.68 1251.75,902.1 1300.82,951.18 1436.07,951.18 1496.62,890.63 R4.2@1496.62,857.13
FTDI_SDOUT: J1.2 R4.1 R5.2 U3.17 | length 497.5
  Top Layer w8: U3.17@1153.3,600.18 1234.18,600.18 1275.25,641.25 1275.25,748.38 J1.2@1328,801.13 1448.38,801.13 R5.2@1449.38,802.13 R4.1@1449.38,857.13
FTDI_SUSPEND: TP2.1 U3.36 | length 1288.7
  Top Layer w10: v3(1001.03,901.6) 1022.4,922.97 U3.36@1022.4,967.3 ; v3(1334,1141.49) TP2.1@1334,1209.2
  Bottom Layer w10: v3(1001.03,901.6) 1001.03,707.88 1105,603.9 1332.7,603.9 1382.1,653.3 1382.1,1093.39 v3(1334,1141.49)
GND: C1.2 C2.2 C3.2 C4.2 C5.2 C6.2 C7.2 C8.2 C9.2 C10.1 C11.2 C12.2 C13.1 C14.1 C15.1 C16.2 C17.2 C18.2 C19.2 C20.2 C21.2 C22.2 C23.2 C24.2 C25.2 C26.2 C27.2 C28.2 C29.2 C30.2 C31.2 C32.2 C33.2 C34.2 C35.2 C36.2 C37.2 C38.2 C39.2 C40.2 C41.2 C42.2 C43.2 C44.2 C45.2 C46.2 C47.2 C48.2 C49.2 C50.2 C51.2 C52.2 C53.2 C54.2 C55.2 C56.2 C57.2 C58.2 C59.2 C60.2 C61.2 C62.2 C63.2 C64.2 C65.2 C66.2 C67.2 C68.2 C69.2 C70.2 C71.2 C72.2 C73.2 C74.2 C75.2 C76.2 C77.2 C78.2 C79.2 C80.2 C81.2 C82.2 C83.2 C84.2 C85.2 C86.2 C87.2 C88.2 C89.2 C90.2 C91.2 C92.2 C93.2 C94.2 C95.2 C96.2 D1.1 D2.1 D3.1 D4.1 D5.1 D6.1 D7.1 D8.1 D9.1 J1.3 J2.5 J2.6 J2.7 J2.8 J2.9 J3.2 J3.3 J4.2 J4.3 J5.2 J5.3 J6.2 J8.2 J9.2 J10.2 J11.9 J11.10 J11.11 J13.2 J13.3 J13.4 J13.5 J14.2 J15.2 J16.9 J16.10 J16.11 J17.2 J18.2 J19.9 J19.10 J19.11 J20.2 J21.2 J22.9 J22.10 J22.11 J23.1 J23.4 J23.7 J23.13 J23.16 J23.19 J23.20 J23.23 J23.26 J23.32 J23.35 J23.38 J23.39 J23.42 J23.45 J23.51 J23.54 J23.57 J23.58 J23.61 J23.64 J23.70 J23.73 J23.76 J23.77 J23.78 J23.79 J23.80 J23.81 J23.82 J24.3 J26.2 J26.4 J26.6 J26.8 J26.10 J27.1 J27.2 J27.3 J27.4 J27.5 J27.6 J27.7 J27.8 J27.9 J27.10 J28.2 J28.4 J28.6 J28.8 J28.10 J28.12 R6.1 R9.1 R19.1 R25.1 R42.1 R50.1 R52.2 R53.2 R57.2 R64.2 R65.2 R69.2 R74.2 R75.2 R79.2 R84.2 R85.2 R89.2 R99.1 R100.1 R101.1 R102.1 R103.1 S1.5 S2.5 S3.5 S4.5 TP4.1 U1.2 U2.11 U2.21 U3.1 U3.5 U3.10 U3.11 U3.13 U3.15 U3.25 U3.35 U3.47 U3.51 U4.11 U4.21 U5.5 U6.1 U6.2 U7.2 U8.1 U8.2 U9.2 U10.8 U10.9 U11.5 U11.6 U11.7 U11.12 U12.2 U13.5 U13.6 U13.7 U13.12 U14.2 U15.A1 U15.A3 U15.A5 U15.A7 U15.A9 U15.B1 U15.B3 U15.B5 U15.B7 U15.B9 U15.C1 U15.C2 U15.C3 U15.C4 U15.C5 U15.C6 U15.C7 U15.C8 U15.C9 U15.G1 U15.G2 U15.G3 U15.G4 U15.G5 U15.G6 U15.G7 U15.G8 U15.G9 U15.H1 U15.H3 U15.H5 U15.H7 U15.H9 U15.J1 U15.J3 U15.J5 U15.J7 U15.J9 U16.A1 U16.A3 U16.A5 U16.A7 U16.A9 U16.B1 U16.B3 U16.B5 U16.B7 U16.B9 U16.C1 U16.C2 U16.C3 U16.C4 U16.C5 U16.C6 U16.C7 U16.C8 U16.C9 U16.G1 U16.G2 U16.G3 U16.G4 U16.G5 U16.G6 U16.G7 U16.G8 U16.G9 U16.H1 U16.H3 U16.H5 U16.H7 U16.H9 U16.J1 U16.J3 U16.J5 U16.J7 U16.J9 U17.A1 U17.A3 U17.A5 U17.A7 U17.A9 U17.B1 U17.B3 U17.B5 U17.B7 U17.B9 U17.C1 U17.C2 U17.C3 U17.C4 U17.C5 U17.C6 U17.C7 U17.C8 U17.C9 U17.G1 U17.G2 U17.G3 U17.G4 U17.G5 U17.G6 U17.G7 U17.G8 U17.G9 U17.H1 U17.H3 U17.H5 U17.H7 U17.H9 U17.J1 U17.J3 U17.J5 U17.J7 U17.J9 U18.A1 U18.A3 U18.A5 U18.A7 U18.A9 U18.B1 U18.B3 U18.B5 U18.B7 U18.B9 U18.C1 U18.C2 U18.C3 U18.C4 U18.C5 U18.C6 U18.C7 U18.C8 U18.C9 U18.G1 U18.G2 U18.G3 U18.G4 U18.G5 U18.G6 U18.G7 U18.G8 U18.G9 U18.H1 U18.H3 U18.H5 U18.H7 U18.H9 U18.J1 U18.J3 U18.J5 U18.J7 U18.J9 Y1.2 Y1.4 Y2.2 | length 6332
  Top Layer w10: v2(218.95,888.8) 230.43,877.32 U5.5@230.43,854.43 ; U11.12@219.54,3544.31 v2(219.54,3569.54) ; U3.51@714.33,856.08 v2(777.99,856.08) ; U3.1@786.18,528.33 v2(786.18,591.99) ; v2(805.86,903.64) U3.47@805.86,967.3 ; U3.5@864.92,528.33 v2(864.92,591.99) ; U3.10@963.34,528.33 U3.11@983.03,528.33 v2(983.03,591.99) ; U3.13@1022.4,528.33 v2(1022.4,591.99) ; v2(1042.08,903.64) U3.35@1042.08,967.3 ; U3.15@1061.77,528.33 v2(1061.77,591.99) ; v2(1089.64,757.66) U3.25@1153.3,757.66 ; v5@2841.87,1568.65 U16.A3@2851.02,1568.65 U16.B3@2882.51,1568.65 U16.C3@2914.01,1568.65 U16.C2@2914.01,1537.16 ; v5@2841.87,1694.64 U16.A7@2851.02,1694.64 U16.B7@2882.51,1694.64 U16.C7@2914.01,1694.64 U16.C6@2914.01,1663.14 ; v5@2841.87,2148.77 U15.C3@2914.01,2148.77 ; v5@2841.87,2274.76 U15.A7@2851.02,2274.76 U15.C7@2914.01,2274.76 U15.C6@2914.01,2243.26 ; v5@2841.87,2728.89 U17.J7@2851.02,2728.89 U17.H7@2882.51,2728.89 U17.G7@2914.01,2728.89 U17.G8@2914.01,2697.39 ; v5@2841.87,3434.99 U18.J3@2851.02,3434.99 U18.H3@2882.51,3434.99 U18.G3@2914.01,3434.99 U18.G4@2914.01,3403.5 ; v5@2851.02,1496.52 U16.A1@2851.02,1505.66 U16.B1@2882.51,1505.66 U16.C1@2914.01,1505.66 ; U16.A5@2851.02,1631.65 U16.B5@2882.51,1631.65 U16.C5@2914.01,1631.65 U16.C4@2914.01,1600.15 v5@2914.01,1591.01 ; v5@2851.02,1766.77 U16.A9@2851.02,1757.63 U16.B9@2882.51,1757.63 U16.C9@2914.01,1757.63 U16.C8@2914.01,1726.13 ; v5@2851.02,2076.64 U15.A1@2851.02,2085.78 U15.B1@2882.51,2085.78 U15.C1@2914.01,2085.78 ; U15.A5@2851.02,2211.76 U15.B5@2882.51,2211.76 U15.C5@2914.01,2211.76 2914.01,2171.13 U15.C4@2914.01,2180.27 ; v5@2851.02,2346.89 U15.A9@2851.02,2337.75 U15.C9@2914.01,2337.75 U15.C8@2914.01,2306.25 ; v5@2851.02,2656.76 U17.J9@2851.02,2665.9 U17.H9@2882.51,2665.9 U17.G9@2914.01,2665.9 ; U17.J5@2851.02,2791.88 U17.H5@2882.51,2791.88 U17.G5@2914.01,2791.88 U17.G6@2914.01,2760.39 v5@2914.01,2751.24 ; U17.J3@2851.02,2854.87 U17.H3@2882.51,2854.87 U17.G3@2914.01,2854.87 U17.G4@2914.01,2823.38 v5@2914.01,2814.24 ; v5@2851.02,2927.01 U17.J1@2851.02,2917.87 U17.H1@2882.51,2917.87 U17.G1@2914.01,2917.87 U17.G2@2914.01,2886.37 ; v5@2851.02,3236.87 U18.J9@2851.02,3246.02 U18.H9@2882.51,3246.02 U18.G9@2914.01,3246.02 ; U18.J7@2851.02,3309.01 U18.H7@2882.51,3309.01 U18.G7@2914.01,3309.01 U18.G8@2914.01,3277.51 v5@2914.01,3268.37 ; U18.J5@2851.02,3372 U18.H5@2882.51,3372 U18.G5@2914.01,3372 v5@2914.01,3331.36 ; v5@2851.02,3507.13 U18.J1@2851.02,3497.98 U18.H1@2882.51,3497.98 U18.G1@2914.01,3497.98 U18.G2@2914.01,3466.49 ; U15.C2@2914.01,2117.28 U15.C3@2914.01,2148.77 ; v5(2914.13,2171.01) 2914.13,2148.89 U15.C3@2914.01,2148.77 ; U16.G1@3039.99,1505.66 U16.H1@3071.49,1505.66 U16.J1@3102.98,1505.66 v5@3112.13,1505.66 ; U16.G2@3039.99,1537.16 U16.G3@3039.99,1568.65 U16.J3@3102.98,1568.65 v5@3112.13,1568.65 ; U16.G4@3039.99,1600.15 U16.G5@3039.99,1631.65 U16.H5@3071.49,1631.65 U16.J5@3102.98,1631.65 v5@3112.13,1631.65 ; U16.G6@3039.99,1663.14 U16.G7@3039.99,1694.64 U16.H7@3071.49,1694.64 U16.J7@3102.98,1694.64 v5@3112.13,1694.64 ; U16.G8@3039.99,1726.13 U16.G9@3039.99,1757.63 U16.H9@3071.49,1757.63 U16.J9@3102.98,1757.63 v5@3102.98,1766.77 ; U15.G1@3039.99,2085.78 U15.H1@3071.49,2085.78 U15.J1@3102.98,2085.78 v5@3112.13,2085.78 ; U15.G2@3039.99,2117.28 U15.G3@3039.99,2148.77 U15.J3@3102.98,2148.77 v5@3112.13,2148.77 ; U15.G4@3039.99,2180.27 U15.G5@3039.99,2211.76 U15.J5@3102.98,2211.76 v5@3112.13,2211.76 ; U15.G6@3039.99,2243.26 U15.G7@3039.99,2274.76 U15.H7@3071.49,2274.76 v5@3112.13,2274.76 ; U15.G8@3039.99,2306.25 U15.G9@3039.99,2337.75 U15.H9@3071.49,2337.75 U15.J9@3102.98,2337.75 ; U17.C9@3039.99,2665.9 U17.B9@3071.49,2665.9 U17.A9@3102.98,2665.9 v5@3112.13,2665.9 ; U17.C8@3039.99,2697.39 U17.C7@3039.99,2728.89 U17.A7@3102.98,2728.89 v5@3112.13,2728.89 ; U17.C6@3039.99,2760.39 U17.C5@3039.99,2791.88 U17.B5@3071.49,2791.88 U17.A5@3102.98,2791.88 v5@3112.13,2791.88 ; U17.C4@3039.99,2823.38 U17.C3@3039.99,2854.87 U17.B3@3071.49,2854.87 U17.A3@3102.98,2854.87 v5@3112.13,2854.87 ; U17.C2@3039.99,2886.37 U17.C1@3039.99,2917.87 U17.B1@3071.49,2917.87 U17.A1@3102.98,2917.87 v5@3102.98,2927.01 ; U18.C9@3039.99,3246.02 U18.B9@3071.49,3246.02 U18.A9@3102.98,3246.02 v5@3112.13,3246.02 ; U18.C8@3039.99,3277.51 U18.C7@3039.99,3309.01 U18.A7@3102.98,3309.01 v5@3112.13,3309.01 ; U18.C6@3039.99,3340.5 U18.C5@3039.99,3372 U18.B5@3071.49,3372 U18.A5@3102.98,3372 v5@3112.13,3372 ; U18.C4@3039.99,3403.5 U18.C3@3039.99,3434.99 U18.B3@3071.49,3434.99 U18.A3@3102.98,3434.99 v5@3112.13,3434.99 ; U18.C2@3039.99,3466.49 U18.C1@3039.99,3497.98 U18.B1@3071.49,3497.98 U18.A1@3102.98,3497.98 v5@3102.98,3507.13
  Top Layer w15: U10.8@217.1,4054.91 260.64,4054.91 v2(272.65,4042.9) ; v2(393.84,4042.9) 405.85,4054.91 U10.9@449.39,4054.91 ; U13.12@787.16,3541.07 v2(787.16,3566.3)
  Top Layer w20: v2(31.4,3478.86) C44.2@61.97,3478.86 ; v2(70.81,775) C19.2@101.38,775 ; v2(276.54,3632.7) U12.2@307.11,3632.7 U12.2@358.29,3632.7 ; U1.2@340.53,1209.2 v2(340.53,1243.77) ; R42.1@354.62,3499.36 v2(385.19,3499.36) ; v2(594.35,1229.94) C13.1@624.91,1229.94 ; v2(600.65,3475.62) C49.2@631.21,3475.62 ; R50.1@946.33,3495.54 v2(976.9,3495.54) ; C9.2@1246.32,1414.04 v2(1246.32,1444.6) ; C10.1@1280.09,1102.3 v2(1310.66,1102.3) ; v2(1336.68,3526.82) R19.1@1367.25,3526.82 ; C23.2@1337.83,4387.6 v2(1368.4,4387.6) ; v2(1886.97,3509.56) R25.1@1917.54,3509.56 ; C29.2@1912,4054.01 v2(1912,4084.58) ; C24.2@1918.62,4392.5 v2(1949.19,4392.5) ; v3(2132.12,3158.4) C39.2@2188.98,3158.4 ; v2(2206.74,566.51) Y2.2@2206.74,597.07 ; v2(2916.89,2542.3) R75.2@2947.45,2542.3 ; R74.2@2945.39,3078.56 v2(2945.39,3109.12) ; v2(3019.76,1351.7) R64.2@3019.76,1382.26 ; R65.2@3097.59,1819.74 v2(3128.15,1819.74)
  Top Layer w25: J23.81@1401.38,2153.32 v2(1401.38,2196.53) ; v2(1401.38,2775.47) J23.78@1401.38,2818.68 ; C95.2@1697.1,1241.14 1697.1,1271.95 v2(1698.09,1272.94) ; J23.82@2279.72,2143.87 v2(2322.93,2143.87) ; J23.77@2279.72,2828.13 v2(2322.93,2828.13)
  Top Layer w30: v2(462.4,3291.58) D8.1@462.4,3340.39 ; v2(607.3,3784.97) D7.1@607.3,3833.78 ; D4.1@607.3,4428.58 v2(607.3,4477.39) ; v2(658.39,376.17) Y1.4@658.39,424.98 ; D1.1@1853.12,4294.89 v2(1853.12,4343.7) ; C26.2@2042.12,4120.32 v2(2042.12,4163.52)
  Bottom Layer w20: v2(70.81,775) C20.2@101.38,775 ; C43.2@463.54,3606.6 463.54,3656.5 C41.2@463.83,3656.78 v2(501.5,3656.78) ; C42.2@463.88,3552.6 468.72,3547.76 505.17,3547.76 ; v3(580.05,519.47) C22.2@606.61,519.47 ; C28.2@1851.77,4053.05 1851.77,4083.62 ; C30.2@1912,4054.01 v2(1912,4084.58) ; v3(2153.6,3316.7) C38.2@2188.36,3316.7 ; v2(2945.39,3109.12) 2945.5,3109.24 R85.2@2945.5,3139.76
  Bottom Layer w25: C96.2@1698.09,1233.63 v2(1698.09,1272.94)
  Bottom Layer w30: C27.2@2042.12,4120.32 v2(2042.12,4163.52)
  other v1: 2886.92,440.99 3044.4,440.99 3201.89,440.99 3359.36,440.99 3516.84,440.99 3674.32,440.99 3831.81,440.99 3989.29,440.99 2856.3,453.68 2917.55,453.68 3013.78,453.68 3075.03,453.68 3171.26,453.67 3232.51,453.68 3328.74,453.68 3389.99,453.67 3486.22,453.67 3547.47,453.68 3643.7,453.68 3704.95,453.67 3801.18,453.68 3862.43,453.68 3958.66,453.68 4019.91,453.68 2843.62,484.3 2930.23,484.3 3001.1,484.3 3087.71,484.3 3158.58,484.3 3245.19,484.3 3316.06,484.3 3402.67,484.3 3473.54,484.3 3560.15,484.3 3631.02,484.3 3717.63,484.3 3788.5,484.3 3875.11,484.3 3945.98,484.3 4032.59,484.3 2854.64,516.19 2919.21,516.19 3012.12,516.19 3076.69,516.19 3169.6,516.19 3234.17,516.19 3327.08,516.19 3391.65,516.19 3484.56,516.19 3549.13,516.19 3642.04,516.19 3706.61,516.19 3799.52,516.19 3864.09,516.19 3957,516.19 4021.57,516.19 2854.64,548.08 2919.21,548.08 3012.12,548.08 3076.69,548.08 3169.6,548.08 3234.17,548.08 3327.08,548.08 3391.65,548.08 3484.56,548.08 3549.13,548.08 3642.04,548.08 3706.61,548.08 3799.52,548.08 3864.09,548.08 3957,548.08 4021.57,548.08 2854.64,579.97 2919.21,579.97 2965.67,579.97 3012.12,579.97 3076.69,579.97 3123.15,579.97 3169.6,579.97 3234.17,579.97 3280.63,579.97 3327.08,579.97 3391.65,579.97 3438.11,579.97 3484.56,579.97 3549.13,579.97 3595.59,579.97 3642.04,579.97 3706.61,579.97 3753.07,579.97 3799.52,579.97 3864.09,579.97 3910.55,579.97 3957,579.97 4021.57,579.97 4486.94,872.7 4391.27,883.73 4423.16,883.73 4455.05,883.73 4517.56,885.39 4530.25,916.01 4517.56,946.63 4391.27,948.29 4423.16,948.29 4455.05,948.29 4486.94,959.32 4391.27,994.76 4486.94,1030.18 4391.27,1041.21 4423.16,1041.21 4455.05,1041.21 4517.56,1042.87 4530.25,1073.49 4517.56,1104.11 4391.27,1105.77 4423.16,1105.77 4455.05,1105.77 4486.94,1116.8 4391.27,1152.24 4486.94,1187.66 4391.27,1198.69 4423.16,1198.69 4455.05,1198.69 4517.56,1200.35 4530.25,1230.97 4517.56,1261.59 4391.27,1263.25 4423.16,1263.25 4455.05,1263.25 4486.94,1274.28 4391.27,1309.72 4486.94,1345.14 4391.27,1356.17 4423.16,1356.17 4455.05,1356.17 4517.56,1357.83 4530.25,1388.45 4517.56,1419.07 4391.27,1420.73 4423.16,1420.73 4455.05,1420.73 4486.94,1431.76 4391.27,1467.2 4486.94,1502.62 4391.27,1513.65 4423.16,1513.65 4455.05,1513.65 4517.56,1515.31 4530.25,1545.93 4517.56,1576.55 4391.27,1578.21 4423.16,1578.21 4455.05,1578.21 4486.94,1589.24 4391.27,1624.68 4486.94,1660.1 4391.27,1671.13 4423.16,1671.13 4455.05,1671.13 4517.56,1672.79 4530.25,1703.41 4517.56,1734.03 4391.27,1735.69 4423.16,1735.69 4455.05,1735.69 4486.94,1746.72 4391.27,1782.16 4486.94,1817.58 4391.27,1828.61 4423.16,1828.61 4455.05,1828.61 4517.56,1830.27 4530.25,1860.89 4517.56,1891.51 4391.27,1893.17 4423.16,1893.17 4455.05,1893.17 4486.94,1904.2 4391.27,1939.64 4486.94,1975.06 4391.27,1986.09 4423.16,1986.09 4455.05,1986.09 4517.56,1987.75 4530.25,2018.37 4517.56,2048.99 4391.27,2050.66 4423.16,2050.66 4455.05,2050.65 4486.94,2061.68 4486.94,2941.97 4391.27,2952.99 4423.16,2952.99 4455.05,2952.99 4517.56,2954.65 4530.25,2985.27 4517.56,3015.9 4391.27,3017.56 4423.16,3017.56 4455.05,3017.56 4486.94,3028.58 4391.27,3064.02 4486.94,3099.45 4391.27,3110.47 4423.16,3110.47 4455.05,3110.47 4517.56,3112.13 4530.25,3142.75 4517.56,3173.38 4391.27,3175.04 4423.16,3175.04 4455.05,3175.04 4486.94,3186.06 4391.27,3221.5 4486.94,3256.93 4391.27,3267.95 4423.16,3267.95 4455.05,3267.95 4517.56,3269.61 4530.25,3300.24 4517.56,3330.86 4391.27,3332.52 4423.16,3332.52 4455.05,3332.52 4486.94,3343.54 4391.27,3378.98 4486.94,3414.41 4391.27,3425.43 4423.16,3425.43 4455.05,3425.43 4517.56,3427.09 4530.25,3457.72 4517.56,3488.34 4391.27,3490 4423.16,3490 4455.05,3490 4486.94,3501.02 4391.27,3536.46 4486.94,3571.89 4391.27,3582.91 4423.16,3582.91 4455.05,3582.91 4517.56,3584.57 4530.25,3615.19 4517.56,3645.82 4391.27,3647.48 4423.16,3647.48 4455.05,3647.48 4486.94,3658.5 4391.27,3693.94 4486.94,3729.37 4391.27,3740.39 4423.16,3740.39 4455.05,3740.39 4517.56,3742.05 4530.25,3772.67 4517.56,3803.3 4391.27,3804.96 4423.16,3804.96 4455.05,3804.96 4486.94,3815.98 4391.27,3851.42 4486.94,3886.85 4391.27,3897.87 4423.16,3897.87 4455.05,3897.87 4517.56,3899.53 4530.25,3930.16 4517.56,3960.78 4391.27,3962.44 4423.16,3962.44 4455.05,3962.44 4486.94,3973.46 4391.27,4008.9 4486.94,4044.33 4391.27,4055.35 4423.16,4055.35 4455.05,4055.35 4517.56,4057.01 4530.25,4087.64 4517.56,4118.26 4391.27,4119.92 4423.16,4119.92 4455.05,4119.92 4486.94,4130.94 2854.64,4423.68 2919.21,4423.68 2965.66,4423.68 3012.12,4423.68 3076.69,4423.68 3123.14,4423.68 3169.6,4423.68 3234.17,4423.68 3280.62,4423.68 3327.08,4423.68 3391.65,4423.68 3438.1,4423.68 3484.56,4423.68 3549.13,4423.68 3595.58,4423.68 3642.04,4423.68 3706.61,4423.68 3753.06,4423.68 3799.52,4423.68 3864.09,4423.68 3910.54,4423.68 3957,4423.68 4021.57,4423.68 2854.64,4455.57 2919.21,4455.57 3012.12,4455.57 3076.69,4455.57 3169.6,4455.57 3234.17,4455.57 3327.08,4455.57 3391.65,4455.57 3484.56,4455.57 3549.13,4455.57 3642.04,4455.57 3706.61,4455.57 3799.52,4455.57 3864.09,4455.57 3957,4455.57 4021.57,4455.57 2854.64,4487.46 2919.21,4487.46 3012.12,4487.46 3076.69,4487.46 3169.6,4487.46 3234.17,4487.46 3327.08,4487.46 3391.65,4487.46 3484.56,4487.46 3549.13,4487.46 3642.04,4487.46 3706.61,4487.46 3799.52,4487.46 3864.09,4487.46 3957,4487.46 4021.57,4487.46 2843.62,4519.35 2930.23,4519.35 3001.1,4519.35 3087.71,4519.35 3158.58,4519.35 3245.19,4519.35 3316.06,4519.35 3402.67,4519.35 3473.54,4519.35 3560.15,4519.35 3631.02,4519.35 3717.63,4519.35 3788.5,4519.35 3875.11,4519.35 3945.98,4519.35 4032.59,4519.35 2856.3,4549.97 2917.55,4549.97 3013.78,4549.97 3075.03,4549.97 3171.26,4549.97 3232.51,4549.97 3328.74,4549.97 3389.99,4549.97 3486.22,4549.97 3547.47,4549.97 3643.7,4549.97 3704.95,4549.97 3801.18,4549.97 3862.43,4549.97 3958.66,4549.97 4019.91,4549.97 2886.92,4562.65 3044.4,4562.65 3201.88,4562.65 3359.36,4562.65 3516.84,4562.65 3674.32,4562.65 3831.81,4562.65 3989.28,4562.65
  other v2: 701.47,38.95 701.47,88.95 701.47,138.95 1046.7,223.93 563.05,235.3 613.05,235.3 1086.65,247.57 1046.7,273.92 1086.65,297.57 1094.65,338.47 1144.65,338.47 1194.65,338.47 1176.7,379.95 418.32,529.8 418.32,579.8 468.32,579.8 518.32,579.8 418.32,629.8 418.32,679.8 397.7,983.72 397.7,1033.72 2382.62,1080.1 397.7,1083.72 2382.62,1130.1 2552.62,1321.56 455.18,1357.82 505.17,1357.82 2552.62,1371.56 303.02,1463.18 353.02,1463.18 1846,1677.25 1946,1677.25 2056.57,1677.25 2156.57,1677.25 3010.88,2485.07 3060.88,2485.07 86.08,3150.43 136.08,3150.43 186.08,3150.43 2507.85,3390.07 180.15,3407.12 230.15,3407.12 747.77,3423.89 797.77,3423.89 2507.85,3440.07 2577.6,3613.76 2125.1,3648.43 2175.1,3648.43 1589.37,3663.98 1639.38,3663.98 2577.6,3663.76 1601.1,3715.32 2020.85,3729.69 2101.7,3730.35 1601.1,3765.32 1349.53,3912.02 1399.52,3912.02 876.7,4056.6 876.7,4106.6 876.7,4156.6 876.7,4206.6
  other v3: 1848.65,3174.6 1377.09,3189.76 1920.12,3266.7 1094.52,3304.36 1389.9,3315.6 1094.7,3360.45
  other v4: 1909.16,2194.66 1933.66,2194.66 1958.16,2194.66 2024.52,2194.66 2049.02,2194.66 2073.51,2194.66 2139.87,2210.41 2164.37,2210.41 2188.87,2210.41 2255.23,2210.41 2279.72,2210.41 2304.22,2210.41 1909.16,2289.15 1933.66,2289.15 1958.16,2289.15 2024.52,2289.15 2049.02,2289.15 2073.51,2289.15 2139.87,2304.9 2164.37,2304.9 2188.87,2304.9 2255.23,2304.9 2279.72,2304.9 2304.22,2304.9 1909.16,2383.64 1933.66,2383.64 1958.16,2383.64 2024.52,2383.64 2049.02,2383.64 2073.51,2383.64 2139.87,2399.39 2164.37,2399.39 2188.87,2399.39 2255.23,2399.39 2279.72,2399.39 2304.22,2399.39 1909.16,2572.61 1933.66,2572.61 1958.16,2572.61 2024.52,2572.61 2049.02,2572.61 2073.51,2572.61 2139.87,2588.36 2164.37,2588.36 2188.87,2588.36 2255.23,2588.36 2279.72,2588.36 2304.22,2588.36 1909.16,2667.1 1933.66,2667.1 1958.16,2667.1 2024.52,2667.1 2049.02,2667.1 2073.51,2667.1 2139.87,2682.85 2164.37,2682.85 2188.87,2682.85 2255.23,2682.85 2279.72,2682.85 2304.22,2682.85 1909.16,2761.59 1933.66,2761.59 1958.16,2761.59 2024.52,2761.59 2049.02,2761.59 2073.51,2761.59 2139.87,2777.34 2164.37,2777.34 2188.87,2777.34 2255.23,2777.34 2279.72,2777.34 2304.22,2777.34
  other v5: 2851.13,1496.4 3112.24,1505.78 2841.76,1568.54 3112.24,1568.77 2914.13,1590.89 3112.24,1631.76 2841.76,1694.52 3112.24,1694.75 2850.9,1766.89 3102.87,1766.89 2851.13,2076.52 3112.24,2085.9 2841.76,2148.65 3112.24,2148.89 3112.24,2211.88 2841.76,2274.64 3112.24,2274.87 3114.97,2337.72 2850.9,2347.01 2851.13,2656.64 3112.24,2666.01 2841.76,2728.77 3112.24,2729.01 2914.13,2751.13 3112.24,2792 2914.13,2814.12 3112.24,2854.99 2850.9,2927.12 3102.87,2927.12 2851.13,3236.76 3112.24,3246.13 2914.13,3268.25 3112.24,3309.12 2914.13,3331.24 3112.24,3372.12 2841.76,3434.87 3112.24,3435.11 2850.9,3507.24 3102.87,3507.24
  other v8: 1082.46,1164.14 831.01,1168.92 1032.26,1194.65 1132.65,1194.65 780.82,1199.43 881.21,1199.43 1082.46,1225.16 831.01,1229.94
